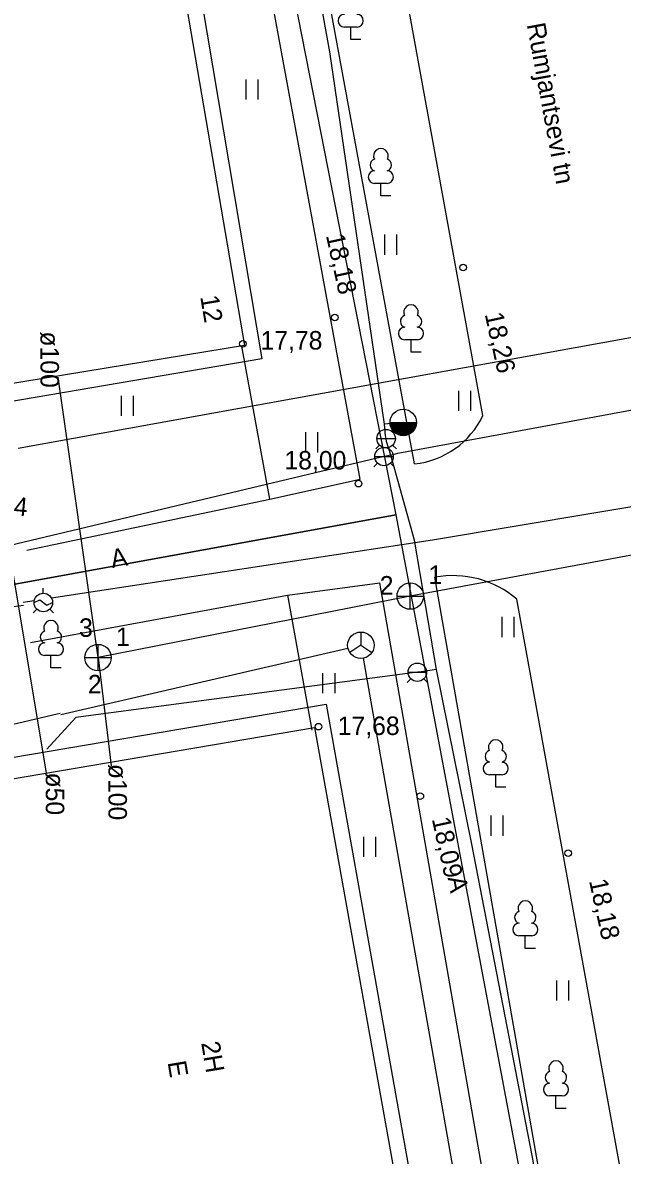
# Model space of a CAD drawing. Extents: x 713497 to 713863, y 6590062 to 6590327.
# Drawn here: x 713632.49 to 713655.17, y 6590099.22 to 6590142.1 of the extents above; entities that cross this region are included whole.
import ezdxf

# ---------------------------------------------------------------- set-up
doc = ezdxf.new("R2010")
doc.units = 0
for name, color, linetype in [('AED', 7, 'Continuous'), ('HALJASTUS', 7, 'Continuous'), ('HOONE', 7, 'Continuous'), ('HOONEDET', 7, 'Continuous'), ('KKAEV', 7, 'Continuous'), ('KORGUS', 7, 'Continuous'), ('KTRASS', 7, 'Continuous'), ('PUU', 7, 'Continuous'), ('SIKAEV', 7, 'Continuous'), ('SITRASS', 7, 'Continuous'), ('TEE', 7, 'Continuous'), ('TORU NR', 7, 'Continuous'), ('VKAEV', 7, 'Continuous'), ('VTRASS', 7, 'Continuous'), ('Слой 1', 7, 'Continuous')]:
    doc.layers.add(name, color=color, linetype=linetype)

msp = doc.modelspace()

# ---------------------------------------------------------------- linework, layer by layer
at = {"layer": 'AED'}
for points in [[(713641.834, 6590124.063), (713640.777, 6590129.855)], [(713642.507, 6590120.434), (713643.424, 6590115.323)]]:
    msp.add_lwpolyline(points, dxfattribs=at)
at = {"layer": 'HALJASTUS'}
for p, q in [((713640.929, 6590139.953), (713640.929, 6590139.192)), ((713641.384, 6590139.953), (713641.384, 6590139.192)), ((713646.173, 6590134.076), (713646.173, 6590133.315)), ((713646.629, 6590134.076), (713646.629, 6590133.315)), ((713636.22, 6590127.976), (713636.22, 6590127.215)), ((713636.675, 6590127.976), (713636.675, 6590127.215)), ((713648.973, 6590128.164), (713648.973, 6590127.403)), ((713649.428, 6590128.164), (713649.428, 6590127.403)), ((713643.188, 6590126.596), (713643.188, 6590125.834)), ((713643.644, 6590126.596), (713643.644, 6590125.834)), ((713650.612, 6590119.605), (713650.612, 6590118.844)), ((713651.067, 6590119.605), (713651.067, 6590118.844)), ((713643.836, 6590117.478), (713643.836, 6590116.717)), ((713644.291, 6590117.478), (713644.291, 6590116.717)), ((713650.198, 6590112.085), (713650.198, 6590111.324)), ((713650.653, 6590112.085), (713650.653, 6590111.324)), ((713645.381, 6590111.279), (713645.381, 6590110.518)), ((713645.836, 6590111.279), (713645.836, 6590110.518)), ((713652.681, 6590105.844), (713652.681, 6590105.083)), ((713653.136, 6590105.844), (713653.136, 6590105.083))]:
    msp.add_line(p, q, dxfattribs=at)
at = {"layer": 'HOONE'}
for p, q in [((713633.272, 6590120.5), (713633.272, 6590120.698)), ((713632.922, 6590120.148), (713633.134, 6590120.254)), ((713633.134, 6590120.254), (713633.411, 6590120.046)), ((713633.411, 6590120.046), (713633.622, 6590120.152)), ((713633.025, 6590119.903), (713632.885, 6590119.763)), ((713633.52, 6590119.903), (713633.659, 6590119.763))]:
    msp.add_line(p, q, dxfattribs=at)
for points in [[(713734.713, 6590179.152), (713722.026, 6590168.127), (713722.157, 6590168.056), (713711.65, 6590159.35), (713701.26, 6590150.68), (713673.462, 6590127.187), (713672.85, 6590126.67), (713647.99, 6590122.51), (713633.578, 6590120.32)], [(713620.755, 6590149.344), (713630.655, 6590151.086), (713637.063, 6590152.231), (713640.875, 6590129.877), (713631.804, 6590128.391), (713624.588, 6590127.182), (713620.755, 6590149.344)], [(713632.322, 6590125.991), (713664.902, 6590131.883)], [(713632.504, 6590120.157), (713632.93, 6590120.222)], [(713625.35, 6590119.07), (713632.517, 6590120.052)], [(713631.21, 6590089.74), (713627.42, 6590112.68), (713643.522, 6590115.42)], [(713643.522, 6590115.42), (713647.628, 6590092.535)]]:
    msp.add_lwpolyline(points, dxfattribs=at)
msp.add_circle((713633.272, 6590120.15), 0.35, dxfattribs=at)
at = {"layer": 'HOONEDET'}
for points in [[(713630.555, 6590151.746), (713637.606, 6590152.762), (713641.533, 6590129.374), (713623.856, 6590126.36), (713622.073, 6590136.806), (713621.833, 6590136.805), (713621.356, 6590139.336), (713621.643, 6590139.419), (713620.79, 6590144.22), (713619.738, 6590149.958), (713630.555, 6590151.746)], [(713628.25, 6590102.12), (713626.11, 6590113.08), (713626.5, 6590113.34), (713643.966, 6590116.303), (713648.317, 6590091.836), (713630.55, 6590088.82), (713628.34, 6590102.19)]]:
    msp.add_lwpolyline(points, dxfattribs=at)
at = {"layer": 'KKAEV'}
for p, q in [((713647.149, 6590119.893), (713647.149, 6590120.893)), ((713646.649, 6590120.393), (713647.649, 6590120.393)), ((713635.341, 6590117.566), (713635.341, 6590118.566)), ((713634.841, 6590118.066), (713635.841, 6590118.066))]:
    msp.add_line(p, q, dxfattribs=at)
for centre in [(713647.149, 6590120.393), (713635.341, 6590118.066)]:
    msp.add_circle(centre, 0.5, dxfattribs=at)
at = {"layer": 'KORGUS'}
for centre in [(713649.15, 6590132.83), (713644.3, 6590130.94), (713640.82, 6590129.94), (713645.19, 6590124.65), (713643.68, 6590115.45), (713647.53, 6590112.82), (713653.12, 6590110.66)]:
    msp.add_circle(centre, 0.125, dxfattribs=at)
at = {"layer": 'KTRASS'}
for p, q in [((713635.341, 6590118.066), (713633.832, 6590128.676)), ((713662.007, 6590123.147), (713647.149, 6590120.393)), ((713647.149, 6590120.393), (713635.341, 6590118.066)), ((713635.341, 6590118.066), (713635.843, 6590113.963))]:
    msp.add_line(p, q, dxfattribs=at)
at = {"layer": 'PUU'}
for p, q in [((713645.137, 6590141.933), (713644.657, 6590141.933)), ((713644.897, 6590141.458), (713644.897, 6590141.933)), ((713645.277, 6590141.458), (713644.897, 6590141.458)), ((713646.278, 6590136.015), (713645.798, 6590136.015)), ((713646.038, 6590135.54), (713646.038, 6590136.015)), ((713646.418, 6590135.54), (713646.038, 6590135.54)), ((713647.419, 6590130.097), (713646.939, 6590130.097)), ((713647.179, 6590129.622), (713647.179, 6590130.097)), ((713647.559, 6590129.622), (713647.179, 6590129.622)), ((713633.802, 6590118.147), (713633.322, 6590118.147)), ((713633.562, 6590117.672), (713633.562, 6590118.147)), ((713633.942, 6590117.672), (713633.562, 6590117.672)), ((713650.622, 6590113.631), (713650.142, 6590113.631)), ((713650.382, 6590113.156), (713650.382, 6590113.631)), ((713650.762, 6590113.156), (713650.382, 6590113.156)), ((713651.741, 6590107.534), (713651.261, 6590107.534)), ((713651.501, 6590107.059), (713651.501, 6590107.534)), ((713651.881, 6590107.059), (713651.501, 6590107.059)), ((713652.9, 6590101.477), (713652.42, 6590101.477)), ((713652.66, 6590101.002), (713652.66, 6590101.477)), ((713653.04, 6590101.002), (713652.66, 6590101.002))]:
    msp.add_line(p, q, dxfattribs=at)
for centre, radius, start, end in [((713644.659, 6590142.17), 0.238, 90.0016, 269.3953), ((713645.134, 6590142.17), 0.238, 270.6047, 89.9984), ((713646.038, 6590137.06), 0.277, 332.5799, 207.4201), ((713645.868, 6590136.712), 0.233, 109.0217, 253.1415), ((713646.208, 6590136.712), 0.233, 286.8508, 70.9859), ((713645.8, 6590136.252), 0.238, 90.0016, 269.3953), ((713646.275, 6590136.252), 0.238, 270.6047, 89.9984), ((713647.179, 6590131.142), 0.277, 332.5799, 207.4201), ((713647.009, 6590130.794), 0.233, 109.0217, 253.1415), ((713647.349, 6590130.794), 0.233, 286.8508, 70.9859), ((713646.941, 6590130.334), 0.238, 90.0016, 269.3953), ((713647.416, 6590130.334), 0.238, 270.6047, 89.9984), ((713633.562, 6590119.192), 0.277, 332.5799, 207.4201), ((713633.392, 6590118.845), 0.233, 109.0217, 253.1415), ((713633.732, 6590118.845), 0.233, 286.8508, 70.9859), ((713633.325, 6590118.385), 0.238, 90.0016, 269.3953), ((713633.8, 6590118.385), 0.238, 270.6047, 89.9984), ((713650.382, 6590114.676), 0.277, 332.5799, 207.4201), ((713650.212, 6590114.329), 0.233, 109.0217, 253.1415), ((713650.552, 6590114.329), 0.233, 286.8508, 70.9859), ((713650.144, 6590113.868), 0.238, 90.0016, 269.3953), ((713650.619, 6590113.868), 0.238, 270.6047, 89.9984), ((713651.501, 6590108.579), 0.277, 332.5799, 207.4201), ((713651.331, 6590108.232), 0.233, 109.0217, 253.1415), ((713651.671, 6590108.232), 0.233, 286.8508, 70.9859), ((713651.264, 6590107.772), 0.238, 90.0016, 269.3953), ((713651.739, 6590107.772), 0.238, 270.6047, 89.9984), ((713652.66, 6590102.522), 0.277, 332.5799, 207.4201), ((713652.489, 6590102.174), 0.233, 109.0217, 253.1415), ((713652.83, 6590102.174), 0.233, 286.8508, 70.9859), ((713652.422, 6590101.714), 0.238, 90.0016, 269.3953), ((713652.897, 6590101.714), 0.238, 270.6047, 89.9984)]:
    msp.add_arc(centre, radius, start, end, dxfattribs=at)
at = {"layer": 'SIKAEV'}
for p, q in [((713645.282, 6590119.032), (713645.282, 6590118.532)), ((713645.282, 6590118.532), (713644.867, 6590118.257)), ((713645.282, 6590118.532), (713645.697, 6590118.257))]:
    msp.add_line(p, q, dxfattribs=at)
msp.add_circle((713645.282, 6590118.532), 0.5, dxfattribs=at)
at = {"layer": 'SITRASS'}
for points in [[(713583.469, 6590179.204), (713587.125, 6590174.133), (713591.164, 6590169.577), (713596.109, 6590163.101), (713600.06, 6590157.809), (713602.836, 6590154.49), (713607.246, 6590149.813), (713612.534, 6590134.682), (713614.495, 6590126.756), (713617.08, 6590112.11), (713617.08, 6590112.12), (713617.47, 6590112.1), (713633.79, 6590115.93), (713633.915, 6590115.958)], [(713633.932, 6590115.917), (713644.794, 6590118.42)], [(713645.368, 6590118.04), (713650.631, 6590088.099)]]:
    msp.add_lwpolyline(points, dxfattribs=at)
at = {"layer": 'TEE'}
for points in [[(713647.309, 6590125.395), (713641.049, 6590159.467)], [(713645.25, 6590124.822), (713638.989, 6590158.893)], [(713649.897, 6590127.23), (713644.271, 6590158.171)], [(713641.834, 6590124.063), (713645.25, 6590124.822)], [(713632.654, 6590122.131), (713641.834, 6590124.063)], [(713654.284, 6590085.754), (713648.083, 6590121.106)], [(713642.507, 6590120.434), (713645.998, 6590120.894)], [(713652.123, 6590085.765), (713645.998, 6590120.894)], [(713632.791, 6590118.631), (713642.507, 6590120.434)], [(713656.94, 6590088.538), (713651.182, 6590120.276)]]:
    msp.add_lwpolyline(points, dxfattribs=at)
for centre, radius, start, end in [((713646.962, 6590128.627), 3.251, 276.1323, 334.537), ((713648.762, 6590117.438), 3.73, 49.5457, 100.4926)]:
    msp.add_arc(centre, radius, start, end, dxfattribs=at)
at = {"layer": 'VKAEV'}
for p, q in [((713646.385, 6590126.965), (713647.385, 6590126.965)), ((713645.99, 6590126.106), (713645.85, 6590125.966)), ((713645.887, 6590126.353), (713646.587, 6590126.353)), ((713646.484, 6590126.106), (713646.624, 6590125.966)), ((713645.808, 6590125.674), (713646.508, 6590125.674)), ((713645.911, 6590125.427), (713645.771, 6590125.287)), ((713646.405, 6590125.427), (713646.545, 6590125.287)), ((713647.069, 6590117.51), (713647.769, 6590117.51)), ((713647.172, 6590117.263), (713647.032, 6590117.123)), ((713647.666, 6590117.263), (713647.806, 6590117.123))]:
    msp.add_line(p, q, dxfattribs=at)
for centre, radius in [((713646.885, 6590126.965), 0.5), ((713646.237, 6590126.353), 0.35), ((713646.158, 6590125.674), 0.35), ((713647.419, 6590117.51), 0.35)]:
    msp.add_circle(centre, radius, dxfattribs=at)
for radius in [0.483, 0.468, 0.45, 0.435, 0.418, 0.403, 0.386, 0.371, 0.354, 0.339, 0.321, 0.306, 0.289, 0.274, 0.257, 0.242, 0.224, 0.209, 0.192, 0.177, 0.16, 0.145, 0.127, 0.112, 0.0951, 0.0801, 0.0628, 0.0478, 0.0328, 0.0178]:
    msp.add_arc((713646.885, 6590126.965), radius, 180, 0, dxfattribs=at)
at = {"layer": 'VTRASS'}
for points in [[(713656.584, 6590071.475), (713656.374, 6590072.423), (713654.566, 6590083.572), (713651.757, 6590099.218), (713649.481, 6590111.002), (713648.142, 6590117.611), (713647.31, 6590122.509), (713646.414, 6590125.725), (713646.252, 6590126.242), (713646.237, 6590126.353), (713646.208, 6590126.464), (713646.178, 6590126.898), (713644.112, 6590140.998), (713641.664, 6590154.51), (713639.62, 6590165.841), (713639.136, 6590167.772), (713636.504, 6590183.972), (713635.775, 6590189.972), (713635.261, 6590195.956), (713632.54, 6590225.141)], [(713646.414, 6590125.725), (713646.679, 6590125.797), (713658.759, 6590128.035), (713673.716, 6590131.088), (713674.021, 6590131.131)], [(713646.885, 6590126.965), (713646.545, 6590126.94), (713646.423, 6590126.926), (713646.178, 6590126.898)], [(713646.414, 6590125.725), (713646.237, 6590125.69), (713646.158, 6590125.674), (713632.022, 6590122.314)], [(713633.39, 6590113.7), (713631.96, 6590122.32)], [(713648.142, 6590117.611), (713647.562, 6590117.52), (713647.419, 6590117.51), (713634.501, 6590115.798), (713633.405, 6590114.602)]]:
    msp.add_lwpolyline(points, dxfattribs=at)
at = {"layer": 'Слой 1'}
for points in [[(713605.01, 6590158.14), (713619.31, 6590158.48), (713639.21, 6590161.17), (713646.6, 6590123.47), (713610.16, 6590116.83)], [(713608.74, 6590112.77), (713610.92, 6590113.06), (713610.16, 6590116.83), (713646.6, 6590123.47), (713654.08, 6590083.76), (713613.56, 6590076.54)]]:
    msp.add_lwpolyline(points, close=True, dxfattribs=at)

# ---------------------------------------------------------------- texts
at = {"layer": 'HOONE'}
for s, rotation, p in [('12', 279.6465, (713639.203, 6590131.727)), ('2H', 279.6065, (713639.24, 6590103.483)), ('E', 279.6065, (713637.969, 6590102.748))]:
    msp.add_text(s, height=0.7, rotation=rotation, dxfattribs=at).set_placement(p)
at = {"layer": 'KORGUS'}
for s, p in [('18,18', (713643.957, 6590134.048)), ('18,26', (713649.963, 6590131.064)), ('18,09', (713647.962, 6590111.957)), ('18,18', (713653.907, 6590109.618))]:
    msp.add_text(s, height=0.7, rotation=282.3666, dxfattribs=at).set_placement(p)
for s, p in [('17,78', (713641.486, 6590129.725)), ('18,00', (713642.391, 6590125.185)), ('17,68', (713644.406, 6590115.135))]:
    msp.add_text(s, height=0.7, dxfattribs=at).set_placement(p)
at = {"layer": 'TEE'}
for s, rotation, p in [('Rumjantsevi tn', 280.4511, (713651.553, 6590142.03)), ('A', 10.0227, (713635.881, 6590121.451)), ('A', 280.5835, (713648.558, 6590109.734))]:
    msp.add_text(s, height=0.7, rotation=rotation, dxfattribs=at).set_placement(p)
at = {"layer": 'TORU NR'}
for s, rotation, p in [('ø100', 269.9696, (713633.165, 6590130.412)), ('4', 354.7103, (713632.131, 6590123.46)), ('ø50', 269.9696, (713633.365, 6590113.715)), ('ø100', 269.9696, (713635.735, 6590114.042))]:
    msp.add_text(s, height=0.7, rotation=rotation, dxfattribs=at).set_placement(p)
for s, p in [('1', (713647.837, 6590120.853)), ('2', (713645.994, 6590120.451)), ('3', (713634.624, 6590118.85)), ('1', (713636.02, 6590118.501)), ('2', (713634.958, 6590116.711))]:
    msp.add_text(s, height=0.7, dxfattribs=at).set_placement(p)

doc.saveas('drawing.dxf')
